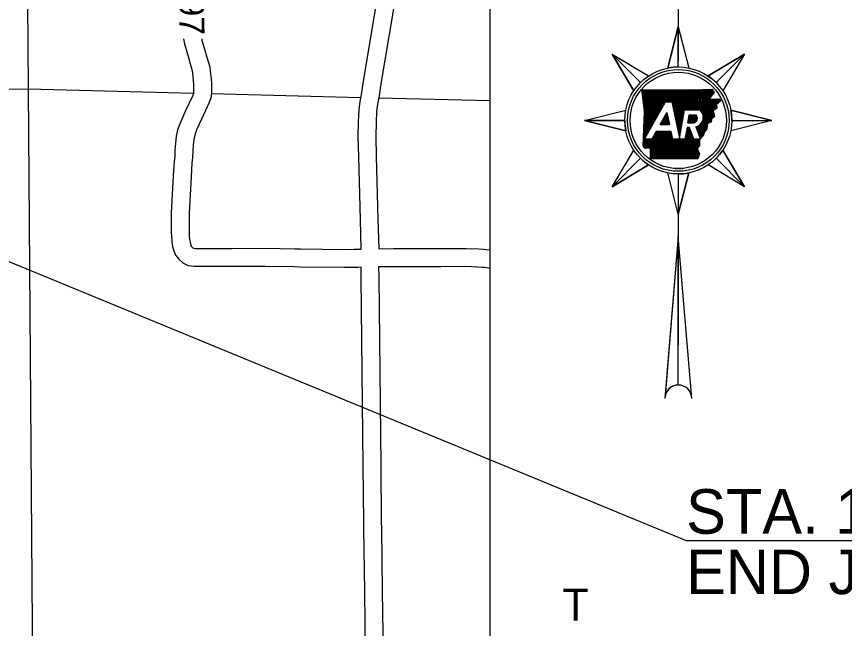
# Model space of a CAD drawing. Extents: x 1373094 to 1376427, y 1168361 to 1170494.
# Drawn here: x 1375231.7 to 1375695.7, y 1168949.6 to 1169292.6 of the extents above; entities that cross this region are included whole.
import ezdxf

# ---------------------------------------------------------------- set-up
doc = ezdxf.new("R2010")
doc.units = 0
for name, color, linetype in [('Default', 7, 'Continuous'), ('R_Axis', 7, 'Continuous'), ('R_Dimension', 7, 'Continuous'), ('R_Draft', 7, 'Continuous'), ('R_No Plot', 7, 'Continuous'), ('R_Water Annot', 7, 'Continuous')]:
    doc.layers.add(name, color=color, linetype=linetype)

msp = doc.modelspace()

# ---------------------------------------------------------------- linework, layer by layer
at = {"layer": 'R_Axis'}
for points in [[(1375491.07, 1169454.85), (1375475.9, 1169417.11), (1375468.56, 1169399.1), (1375453.78, 1169362.61), (1375441.48, 1169330.39), (1375439.61, 1169324.64), (1375437.58, 1169318.47), (1375433.53, 1169301.17), (1375433.08, 1169298.67), (1375425.81, 1169255.31), (1375425.06, 1169250.04)], [(1375496.95, 1169442.66), (1375485.17, 1169413.36), (1375477.82, 1169395.33), (1375463.09, 1169358.95), (1375450.91, 1169327.06), (1375449.11, 1169321.54), (1375447.22, 1169315.76), (1375443.32, 1169299.13), (1375442.93, 1169296.95), (1375435.69, 1169253.77), (1375434.89, 1169248.2)], [(1375237.22, 1169372.94), (1375238.19, 1169252.01), (1375240.86, 1168901.02)], [(1375325.33, 1169280.16), (1375325.76, 1169277.21), (1375328.08, 1169269.56)], [(1375335.45, 1169280.06), (1375335.55, 1169279.38), (1375337.65, 1169272.46)], [(1375337.65, 1169272.46), (1375337.87, 1169271.73), (1375338.51, 1169269.17), (1375339.95, 1169264.25), (1375340.39, 1169260.27), (1375340.69, 1169258.08), (1375340.92, 1169254.67), (1375340.91, 1169250.76), (1375340.7, 1169247.49), (1375339.64, 1169244.31), (1375335.34, 1169235.1), (1375335.34, 1169235.09)], [(1375328.08, 1169269.56), (1375328.23, 1169269.04), (1375328.87, 1169266.54), (1375330.11, 1169262.29), (1375330.46, 1169259.06), (1375330.73, 1169257.06), (1375330.92, 1169254.34), (1375330.91, 1169251.09), (1375330.8, 1169249.42), (1375330.34, 1169248.02), (1375326.28, 1169239.34), (1375326.28, 1169239.33)], [(1374905.85, 1169251.57), (1375238.19, 1169252.01), (1375330.82, 1169249.65)], [(1375340.82, 1169249.4), (1375424.54, 1169247.27)], [(1375425.06, 1169250.04), (1375424.12, 1169245.03), (1375423.48, 1169240.37), (1375423.24, 1169233.54), (1375423.04, 1169225.58), (1375423.34, 1169213.93)], [(1375434.89, 1169248.2), (1375433.99, 1169243.42), (1375433.45, 1169239.51), (1375433.24, 1169233.24), (1375433.04, 1169225.58), (1375433.34, 1169214.18)], [(1375434.67, 1169247.01), (1375496.95, 1169245.43)], [(1375326.28, 1169239.32), (1375324.91, 1169236.38), (1375323.34, 1169232.81), (1375321.98, 1169229.02), (1375321.1, 1169225.45), (1375320.69, 1169221.52), (1375320.43, 1169217.75), (1375320.36, 1169214.16), (1375320.02, 1169211.24), (1375319.56, 1169203.27)], [(1375335.34, 1169235.1), (1375334.02, 1169232.26), (1375332.64, 1169229.11), (1375331.56, 1169226.13), (1375330.97, 1169223.72), (1375330.65, 1169220.65), (1375330.42, 1169217.31), (1375330.35, 1169213.48), (1375329.99, 1169210.38), (1375329.54, 1169202.69)], [(1375433.34, 1169214.18), (1375434.24, 1169178.99)], [(1375423.34, 1169213.93), (1375424.24, 1169178.74)], [(1375319.56, 1169203.27), (1375318.35, 1169182.53), (1375318.39, 1169172.27), (1375318.52, 1169168.96), (1375318.63, 1169167.45)], [(1375329.54, 1169202.69), (1375328.36, 1169182.26), (1375328.39, 1169172.48), (1375328.5, 1169169.52), (1375328.6, 1169168.19)], [(1375424.24, 1169178.74), (1375424.67, 1169162.22)], [(1375434.24, 1169178.99), (1375434.67, 1169162.39)], [(1375328.6, 1169168.19), (1375328.65, 1169167.59), (1375328.92, 1169166.06), (1375329.4, 1169164.46), (1375329.62, 1169163.87), (1375329.99, 1169163.43), (1375330.54, 1169162.94), (1375330.94, 1169162.74), (1375331.9, 1169162.61), (1375352.38, 1169162.65)], [(1375318.63, 1169167.45), (1375318.71, 1169166.34), (1375319.18, 1169163.74), (1375319.92, 1169161.27), (1375320.86, 1169158.76), (1375322.8, 1169156.43), (1375324.9, 1169154.58), (1375327.93, 1169153.07), (1375331.22, 1169152.6), (1375352.4, 1169152.65)], [(1375352.38, 1169162.65), (1375371.2, 1169162.69), (1375387.68, 1169162.38)], [(1375387.68, 1169162.38), (1375390.8, 1169162.33), (1375415.55, 1169162.05), (1375420.65, 1169162.13), (1375422.67, 1169162.17)], [(1375422.67, 1169162.17), (1375424.67, 1169162.22)], [(1375434.67, 1169162.39), (1375443.01, 1169162.47), (1375457.98, 1169162.48)], [(1375457.98, 1169162.48), (1375469.49, 1169162.49), (1375483.64, 1169162.64), (1375490.8, 1169162.35), (1375493.5, 1169162.17)], [(1375493.5, 1169162.17), (1375494.76, 1169162.09), (1375496.95, 1169161.8)], [(1375352.4, 1169152.65), (1375371.12, 1169152.69), (1375387.5, 1169152.38)], [(1375387.5, 1169152.38), (1375390.65, 1169152.33), (1375415.57, 1169152.04), (1375420.84, 1169152.13), (1375422.9, 1169152.17)], [(1375422.9, 1169152.17), (1375424.85, 1169152.22)], [(1375424.91, 1169146.33), (1375424.85, 1169152.22)], [(1375434.84, 1169152.39), (1375443.06, 1169152.47), (1375457.98, 1169152.48)], [(1375434.9, 1169146.43), (1375434.84, 1169152.39)], [(1375457.98, 1169152.48), (1375469.55, 1169152.49), (1375483.49, 1169152.64), (1375490.27, 1169152.36), (1375492.84, 1169152.19)], [(1375492.84, 1169152.19), (1375493.79, 1169152.13), (1375496.46, 1169151.78), (1375496.95, 1169151.68)], [(1375425.26, 1169111.13), (1375424.91, 1169146.33)], [(1375435.26, 1169111.24), (1375434.9, 1169146.43)], [(1375425.62, 1169075.94), (1375425.26, 1169111.13)], [(1375435.62, 1169076.04), (1375435.26, 1169111.24)], [(1375425.98, 1169040.74), (1375425.62, 1169075.94)], [(1375435.98, 1169040.84), (1375435.62, 1169076.04)], [(1375426.35, 1169005.52), (1375426.29, 1169009.47), (1375425.98, 1169040.74)], [(1375436.35, 1169005.66), (1375436.29, 1169009.59), (1375435.98, 1169040.84)], [(1375426.86, 1168970.32), (1375426.35, 1169005.52)], [(1375436.86, 1168970.47), (1375436.35, 1169005.66)], [(1375427.37, 1168935.13), (1375426.86, 1168970.32)], [(1375437.36, 1168935.27), (1375436.86, 1168970.47)]]:
    msp.add_lwpolyline(points, dxfattribs=at)
at = {"layer": 'R_Dimension'}
for p, q in [((1374935.89, 1169275.48), (1375606.99, 1168998.81)), ((1375606.99, 1168998.81), (1375955.75, 1168998.81))]:
    msp.add_line(p, q, dxfattribs=at)
at = {"layer": 'R_Draft'}
for p, q in [((1375602.62, 1169386.03), (1375602.62, 1169267.6)), ((1375602.62, 1169286.82), (1375596.77, 1169263.75)), ((1375602.62, 1169264.32), (1375602.62, 1169286.82)), ((1375565.49, 1169271.45), (1375581.4, 1169255.54)), ((1375581.4, 1169255.54), (1375565.49, 1169271.45)), ((1375565.49, 1169271.45), (1375577.68, 1169251)), ((1375639.74, 1169271.45), (1375619.29, 1169259.26)), ((1375623.83, 1169255.54), (1375639.74, 1169271.45)), ((1375623.83, 1169255.54), (1375639.74, 1169271.45)), ((1375583.67, 1169223.82), (1375595.51, 1169244.72)), ((1375595.51, 1169244.72), (1375599.02, 1169244.72)), ((1375592.38, 1169232.02), (1375596.25, 1169238.86)), ((1375606.16, 1169240.36), (1375614.38, 1169240.36)), ((1375608.73, 1169237.41), (1375612.59, 1169237.41)), ((1375655.12, 1169234.32), (1375632.04, 1169240.17)), ((1375550.12, 1169234.32), (1375572.62, 1169234.32)), ((1375572.62, 1169234.32), (1375550.12, 1169234.32)), ((1375550.12, 1169234.32), (1375573.19, 1169228.48)), ((1375607.95, 1169232.94), (1375611.47, 1169232.94)), ((1375632.62, 1169234.32), (1375655.12, 1169234.32)), ((1375632.62, 1169234.32), (1375655.12, 1169234.32)), ((1375590.21, 1169228.2), (1375587.73, 1169223.82)), ((1375598.53, 1169228.2), (1375590.21, 1169228.2)), ((1375592.38, 1169232.02), (1375597.71, 1169232.02)), ((1375608.94, 1169230.46), (1375607.51, 1169230.46)), ((1375611.4, 1169223.82), (1375608.94, 1169230.46)), ((1375612.42, 1169230.82), (1375615.01, 1169223.82)), ((1375587.73, 1169223.82), (1375583.67, 1169223.82)), ((1375606.36, 1169223.82), (1375599.47, 1169223.82)), ((1375615.01, 1169223.82), (1375611.4, 1169223.82)), ((1375639.74, 1169197.2), (1375627.55, 1169217.65)), ((1375565.49, 1169197.2), (1375581.4, 1169213.11)), ((1375581.4, 1169213.11), (1375565.49, 1169197.2)), ((1375565.49, 1169197.2), (1375585.94, 1169209.39)), ((1375623.83, 1169213.11), (1375639.74, 1169197.2)), ((1375623.83, 1169213.11), (1375639.74, 1169197.2)), ((1375602.62, 1169181.82), (1375608.46, 1169204.9)), ((1375602.61, 1169204.32), (1375602.62, 1169204.33)), ((1375602.62, 1169204.32), (1375602.62, 1169108.29)), ((1375602.62, 1169204.32), (1375602.62, 1169181.82)), ((1375602.62, 1169169.28), (1375595.22, 1169079.77)), ((1375602.62, 1169086.03), (1375602.62, 1169169.28))]:
    msp.add_line(p, q, dxfattribs=at)
for points in [[(1375596.77, 1169263.75), (1375602.62, 1169286.82), (1375608.46, 1169263.75)], [(1375577.68, 1169251), (1375565.49, 1169271.45), (1375585.94, 1169259.26)], [(1375619.29, 1169259.26), (1375639.74, 1169271.45), (1375627.55, 1169251)], [(1375582.13, 1169251.5), (1375593.84, 1169251.49), (1375604.11, 1169251.51), (1375616.23, 1169251.7), (1375621.85, 1169251.83)], [(1375582.98, 1169219.83), (1375583.63, 1169239.47), (1375582.13, 1169251.5)], [(1375599.02, 1169244.72), (1375603.38, 1169224.37), (1375606.16, 1169240.36)], [(1375625.53, 1169246.45), (1375626.54, 1169245.39), (1375624.02, 1169243.32), (1375624.29, 1169241.22), (1375622.12, 1169239.79), (1375622.86, 1169236.57), (1375621.19, 1169235.05), (1375621.04, 1169233.39), (1375619.01, 1169232.66), (1375618.7, 1169229.54), (1375617.24, 1169227.97), (1375616.53, 1169225.62), (1375614.41, 1169223.68), (1375614.57, 1169220.25), (1375613.13, 1169218.63), (1375614.44, 1169215.68), (1375613.53, 1169212.76)], [(1375620.11, 1169246.18), (1375625.61, 1169246.46)], [(1375573.19, 1169228.48), (1375550.12, 1169234.32), (1375573.19, 1169240.17)], [(1375596.25, 1169238.86), (1375597.71, 1169232.02)], [(1375607.95, 1169232.94), (1375608.73, 1169237.41)], [(1375632.04, 1169240.17), (1375655.12, 1169234.32), (1375632.04, 1169228.48)], [(1375599.47, 1169223.82), (1375598.53, 1169228.2)], [(1375607.51, 1169230.46), (1375606.36, 1169223.82)], [(1375585.94, 1169209.39), (1375565.49, 1169197.2), (1375577.68, 1169217.65)], [(1375613.53, 1169212.76), (1375587, 1169212.8), (1375586.98, 1169218.66)], [(1375627.55, 1169217.65), (1375639.74, 1169197.2), (1375619.29, 1169209.39)], [(1375608.46, 1169204.9), (1375602.62, 1169181.82), (1375596.77, 1169204.9)], [(1375610.12, 1169078.53), (1375602.62, 1169169.28), (1375595.12, 1169078.53)]]:
    msp.add_lwpolyline(points, dxfattribs=at)
for radius in [30, 27]:
    msp.add_circle((1375602.62, 1169234.32), radius, dxfattribs=at)
for centre, radius, start, end in [((1375602.62, 1169234.32), 30, 90, 101.2291), ((1375602.62, 1169234.32), 30, 45, 56.2291), ((1375602.62, 1169234.32), 30, 135, 146.2291), ((1375610.63, 1169235.53), 2.72, 288.1268, 43.8902), ((1375611.33, 1169236.02), 5.31, 281.8626, 54.8705), ((1375602.62, 1169234.32), 30, 0, 11.2291), ((1375602.62, 1169234.32), 30, 180, 191.2291), ((1375602.62, 1169234.32), 30, 315, 326.2291), ((1375602.62, 1169234.32), 30, 225, 236.2291), ((1375602.62, 1169234.32), 30, 270, 281.2291), ((1375602.62, 1169078.53), 7.5, 0, 180), ((1375602.62, 1169078.53), 7.5, 90, 170.5511)]:
    msp.add_arc(centre, radius, start, end, dxfattribs=at)
for points in [[(1375621.85, 1169251.83), (1375621.89, 1169251.51), (1375621.99, 1169251.35), (1375622, 1169251.04), (1375622.13, 1169250.91), (1375622.34, 1169250.78), (1375622.52, 1169250.57), (1375622.57, 1169250.33), (1375622.51, 1169250.07), (1375622.49, 1169249.79), (1375622.47, 1169249.54), (1375622.42, 1169249.32), (1375622.25, 1169249.14), (1375622.08, 1169249.01), (1375621.93, 1169248.86), (1375621.82, 1169248.7), (1375621.63, 1169248.52), (1375621.45, 1169248.34), (1375621.29, 1169248.18), (1375621.14, 1169247.98), (1375621.07, 1169247.76), (1375620.9, 1169247.6), (1375620.77, 1169247.45), (1375620.6, 1169247.26), (1375620.51, 1169247.06), (1375620.34, 1169246.84), (1375620.31, 1169246.62), (1375620.2, 1169246.44), (1375620.19, 1169246.42)], [(1375586.98, 1169218.66), (1375587.01, 1169218.64), (1375586.88, 1169218.74), (1375586.69, 1169218.83), (1375586.48, 1169218.85), (1375586.21, 1169218.88), (1375585.99, 1169218.91), (1375585.75, 1169219.06), (1375585.51, 1169218.9), (1375585.23, 1169218.78), (1375585.07, 1169218.91), (1375584.86, 1169218.83), (1375584.72, 1169218.87), (1375584.47, 1169218.7), (1375584.23, 1169218.76), (1375584.05, 1169218.71), (1375583.84, 1169218.72), (1375583.79, 1169218.96), (1375583.58, 1169219), (1375583.4, 1169219.1), (1375583.28, 1169219.35), (1375583.19, 1169219.55), (1375582.98, 1169219.83)]]:
    msp.add_spline(points, degree=3, dxfattribs=at)
at = {"layer": 'R_No Plot'}
msp.add_lwpolyline([(1373989.53, 1169534.16), (1375496.95, 1169534.16), (1375496.95, 1168608.52), (1373989.53, 1168608.52)], close=True, dxfattribs=at)
at = {"layer": 'R_Water Annot'}
for p, q in [((1375582.17, 1169251.23), (1375582.43, 1169251.5)), ((1375582.26, 1169250.48), (1375583.28, 1169251.5)), ((1375582.36, 1169249.72), (1375584.13, 1169251.5)), ((1375582.45, 1169248.97), (1375584.98, 1169251.5)), ((1375582.54, 1169248.22), (1375585.82, 1169251.5)), ((1375582.64, 1169247.46), (1375586.67, 1169251.5)), ((1375582.73, 1169246.71), (1375587.52, 1169251.49)), ((1375582.83, 1169245.95), (1375588.37, 1169251.49)), ((1375582.92, 1169245.2), (1375589.22, 1169251.49)), ((1375583.01, 1169244.44), (1375590.06, 1169251.49)), ((1375583.11, 1169243.69), (1375590.91, 1169251.49)), ((1375583.2, 1169242.93), (1375591.76, 1169251.49)), ((1375583.3, 1169242.18), (1375592.61, 1169251.49)), ((1375583.39, 1169241.42), (1375593.46, 1169251.49)), ((1375583.42, 1169232.97), (1375601.96, 1169251.51)), ((1375583.45, 1169233.84), (1375601.11, 1169251.51)), ((1375583.48, 1169234.72), (1375600.26, 1169251.5)), ((1375583.48, 1169240.67), (1375594.31, 1169251.49)), ((1375583.5, 1169235.6), (1375599.41, 1169251.5)), ((1375583.53, 1169236.48), (1375598.56, 1169251.5)), ((1375583.56, 1169237.36), (1375597.71, 1169251.5)), ((1375583.58, 1169239.92), (1375595.16, 1169251.49)), ((1375583.59, 1169238.23), (1375596.86, 1169251.5)), ((1375583.62, 1169239.11), (1375596.01, 1169251.5)), ((1375596.02, 1169244.72), (1375602.81, 1169251.51)), ((1375596.87, 1169244.72), (1375603.66, 1169251.51)), ((1375597.72, 1169244.72), (1375604.51, 1169251.52)), ((1375598.56, 1169244.72), (1375605.38, 1169251.53)), ((1375599.09, 1169244.4), (1375606.24, 1169251.55)), ((1375599.24, 1169243.7), (1375607.1, 1169251.56)), ((1375599.39, 1169243), (1375607.96, 1169251.57)), ((1375599.54, 1169242.3), (1375608.82, 1169251.59)), ((1375599.69, 1169241.6), (1375609.69, 1169251.6)), ((1375599.84, 1169240.9), (1375610.55, 1169251.61)), ((1375599.99, 1169240.21), (1375611.41, 1169251.63)), ((1375600.14, 1169239.51), (1375612.27, 1169251.64)), ((1375600.29, 1169238.81), (1375613.13, 1169251.65)), ((1375600.44, 1169238.11), (1375614, 1169251.67)), ((1375600.59, 1169237.41), (1375614.86, 1169251.68)), ((1375600.74, 1169236.71), (1375615.72, 1169251.69)), ((1375600.89, 1169236.01), (1375616.58, 1169251.71)), ((1375601.04, 1169235.31), (1375617.45, 1169251.73)), ((1375606.93, 1169240.36), (1375618.32, 1169251.75)), ((1375607.78, 1169240.36), (1375619.19, 1169251.77)), ((1375608.63, 1169240.36), (1375620.06, 1169251.79)), ((1375609.48, 1169240.36), (1375620.93, 1169251.81)), ((1375610.33, 1169240.36), (1375621.8, 1169251.83)), ((1375611.17, 1169240.36), (1375621.99, 1169251.17)), ((1375612.02, 1169240.36), (1375622.4, 1169250.73)), ((1375612.87, 1169240.36), (1375622.51, 1169249.99)), ((1375613.72, 1169240.36), (1375620.57, 1169247.21)), ((1375583.39, 1169232.09), (1375594.84, 1169243.54)), ((1375614.49, 1169240.28), (1375620.4, 1169246.19)), ((1375614.95, 1169239.9), (1375621.3, 1169246.24)), ((1375615.37, 1169239.46), (1375622.19, 1169246.28)), ((1375615.73, 1169238.98), (1375623.08, 1169246.33)), ((1375616.05, 1169238.45), (1375623.98, 1169246.38)), ((1375616.31, 1169237.86), (1375624.87, 1169246.42)), ((1375616.45, 1169234.6), (1375624.15, 1169242.3)), ((1375616.5, 1169237.2), (1375625.68, 1169246.38)), ((1375616.62, 1169236.47), (1375626.08, 1169245.93)), ((1375616.62, 1169235.63), (1375624.05, 1169243.05)), ((1375625.7, 1169244.7), (1375626.47, 1169245.47)), ((1375583.3, 1169229.46), (1375591.51, 1169237.67)), ((1375583.33, 1169230.33), (1375592.62, 1169239.63)), ((1375583.36, 1169231.21), (1375593.73, 1169241.58)), ((1375594.54, 1169235.84), (1375596.48, 1169237.78)), ((1375595.65, 1169237.79), (1375596.33, 1169238.48)), ((1375601.19, 1169234.61), (1375606, 1169239.43)), ((1375601.34, 1169233.91), (1375605.82, 1169238.4)), ((1375601.49, 1169233.22), (1375605.64, 1169237.37)), ((1375607.95, 1169232.94), (1375612.42, 1169237.41)), ((1375608.13, 1169233.97), (1375611.57, 1169237.41)), ((1375608.3, 1169234.99), (1375610.72, 1169237.41)), ((1375608.48, 1169236.02), (1375609.87, 1169237.41)), ((1375608.66, 1169237.05), (1375609.02, 1169237.41)), ((1375612.94, 1169229.4), (1375622.35, 1169238.81)), ((1375613.17, 1169228.78), (1375622.51, 1169238.12)), ((1375613.4, 1169228.16), (1375622.67, 1169237.43)), ((1375615.71, 1169233.01), (1375622.19, 1169239.5)), ((1375623.2, 1169240.5), (1375624.25, 1169241.55)), ((1375583.24, 1169227.7), (1375589.3, 1169233.76)), ((1375583.27, 1169228.58), (1375590.41, 1169235.71)), ((1375592.42, 1169232.02), (1375596.78, 1169236.38)), ((1375593.27, 1169232.02), (1375596.93, 1169235.68)), ((1375593.43, 1169233.88), (1375596.63, 1169237.08)), ((1375594.11, 1169232.02), (1375597.08, 1169234.98)), ((1375594.96, 1169232.02), (1375597.23, 1169234.28)), ((1375595.81, 1169232.02), (1375597.38, 1169233.59)), ((1375596.66, 1169232.02), (1375597.53, 1169232.89)), ((1375601.63, 1169232.52), (1375605.46, 1169236.35)), ((1375601.78, 1169231.82), (1375605.28, 1169235.32)), ((1375601.93, 1169231.12), (1375605.11, 1169234.29)), ((1375602.08, 1169230.42), (1375604.93, 1169233.26)), ((1375608.8, 1169232.94), (1375612.89, 1169237.03)), ((1375609.65, 1169232.94), (1375613.17, 1169236.47)), ((1375610.5, 1169232.94), (1375613.33, 1169235.78)), ((1375611.35, 1169232.94), (1375613.26, 1169234.86)), ((1375613.63, 1169227.54), (1375622.83, 1169236.74)), ((1375619.93, 1169232.99), (1375621.12, 1169234.18)), ((1375583.18, 1169225.95), (1375587.08, 1169229.85)), ((1375583.21, 1169226.82), (1375588.19, 1169231.8)), ((1375583.31, 1169219.28), (1375592.23, 1169228.2)), ((1375583.81, 1169218.94), (1375593.08, 1169228.2)), ((1375584.42, 1169218.7), (1375593.93, 1169228.2)), ((1375585.43, 1169218.86), (1375594.77, 1169228.2)), ((1375586.29, 1169218.87), (1375595.62, 1169228.2)), ((1375586.96, 1169218.69), (1375596.47, 1169228.2)), ((1375586.99, 1169217.02), (1375598.17, 1169228.2)), ((1375586.99, 1169217.87), (1375597.32, 1169228.2)), ((1375588.69, 1169225.52), (1375591.38, 1169228.2)), ((1375589.8, 1169227.47), (1375590.53, 1169228.2)), ((1375597.51, 1169232.02), (1375597.68, 1169232.19)), ((1375602.23, 1169229.72), (1375604.75, 1169232.24)), ((1375602.38, 1169229.02), (1375604.57, 1169231.21)), ((1375602.53, 1169228.32), (1375604.39, 1169230.18)), ((1375602.68, 1169227.62), (1375604.21, 1169229.15)), ((1375602.83, 1169226.93), (1375604.03, 1169228.13)), ((1375606.5, 1169224.66), (1375609.85, 1169228)), ((1375606.68, 1169225.68), (1375609.62, 1169228.62)), ((1375606.86, 1169226.71), (1375609.39, 1169229.24)), ((1375607.04, 1169227.74), (1375609.16, 1169229.86)), ((1375607.22, 1169228.77), (1375608.92, 1169230.46)), ((1375607.4, 1169229.8), (1375608.07, 1169230.46)), ((1375612.49, 1169230.64), (1375612.74, 1169230.9)), ((1375612.71, 1169230.02), (1375614.33, 1169231.63)), ((1375613.86, 1169226.92), (1375618.95, 1169232.01)), ((1375614.09, 1169226.3), (1375618.85, 1169231.07)), ((1375614.32, 1169225.68), (1375618.76, 1169230.12)), ((1375582.99, 1169219.82), (1375586.99, 1169223.82)), ((1375583.01, 1169220.68), (1375586.15, 1169223.82)), ((1375583.04, 1169221.56), (1375585.3, 1169223.82)), ((1375583.07, 1169222.44), (1375584.45, 1169223.82)), ((1375583.1, 1169223.31), (1375583.76, 1169223.98)), ((1375583.13, 1169224.19), (1375584.87, 1169225.93)), ((1375583.16, 1169225.07), (1375585.98, 1169227.89)), ((1375586.99, 1169216.18), (1375598.61, 1169227.8)), ((1375586.99, 1169215.33), (1375598.76, 1169227.1)), ((1375587, 1169214.48), (1375598.91, 1169226.4)), ((1375587, 1169213.64), (1375599.06, 1169225.7)), ((1375587.01, 1169212.8), (1375599.21, 1169225)), ((1375587.86, 1169212.8), (1375599.36, 1169224.31)), ((1375588.71, 1169212.8), (1375599.72, 1169223.82)), ((1375589.55, 1169212.8), (1375600.57, 1169223.82)), ((1375590.4, 1169212.8), (1375601.42, 1169223.82)), ((1375591.25, 1169212.8), (1375602.27, 1169223.82)), ((1375592.09, 1169212.79), (1375603.12, 1169223.82)), ((1375592.94, 1169212.79), (1375603.96, 1169223.82)), ((1375593.79, 1169212.79), (1375604.81, 1169223.82)), ((1375594.64, 1169212.79), (1375605.66, 1169223.82)), ((1375595.48, 1169212.79), (1375610.08, 1169227.38)), ((1375596.33, 1169212.79), (1375610.31, 1169226.76)), ((1375597.18, 1169212.79), (1375610.54, 1169226.14)), ((1375598.02, 1169212.78), (1375610.76, 1169225.52)), ((1375598.87, 1169212.78), (1375610.99, 1169224.9)), ((1375599.72, 1169212.78), (1375611.22, 1169224.29)), ((1375600.57, 1169212.78), (1375611.6, 1169223.82)), ((1375601.41, 1169212.78), (1375612.45, 1169223.82)), ((1375602.26, 1169212.78), (1375613.3, 1169223.82)), ((1375602.98, 1169226.23), (1375603.85, 1169227.1)), ((1375603.11, 1169212.78), (1375614.15, 1169223.82)), ((1375603.13, 1169225.53), (1375603.67, 1169226.07)), ((1375603.28, 1169224.83), (1375603.49, 1169225.04)), ((1375614.55, 1169225.06), (1375617.15, 1169227.66)), ((1375614.77, 1169224.44), (1375616.78, 1169226.45)), ((1375603.95, 1169212.77), (1375614.43, 1169223.25)), ((1375604.8, 1169212.77), (1375614.47, 1169222.44)), ((1375605.65, 1169212.77), (1375614.51, 1169221.63)), ((1375606.5, 1169212.77), (1375614.54, 1169220.82)), ((1375607.34, 1169212.77), (1375613.15, 1169218.58)), ((1375608.19, 1169212.77), (1375613.41, 1169217.99)), ((1375609.04, 1169212.77), (1375613.67, 1169217.4)), ((1375609.88, 1169212.77), (1375613.94, 1169216.82)), ((1375610.73, 1169212.76), (1375614.2, 1169216.23)), ((1375611.58, 1169212.76), (1375614.42, 1169215.6)), ((1375612.43, 1169212.76), (1375614.03, 1169214.37)), ((1375613.27, 1169212.76), (1375613.65, 1169213.14))]:
    msp.add_line(p, q, dxfattribs=at)
msp.add_circle((1375602.62, 1169234.32), 28.5, dxfattribs=at)

# ---------------------------------------------------------------- texts
at = {"layer": 'Default'}
msp.add_text('T', height=18, dxfattribs=at).set_placement((1375537.67, 1168953.98))
at = {"layer": 'R_Dimension'}
for s, p in [('STA. 110+23.00', (1375606.99, 1169002.69)), ('END JOB 070510', (1375606.99, 1168968.83))]:
    msp.add_text(s, height=25, rotation=0.0006, dxfattribs=at).set_placement(p)
at = {"layer": 'R_Draft'}
msp.add_text('DWB 7-27-17', height=0.5833, dxfattribs=at).set_placement((1375600.78, 1169206.82))
at = {"layer": 'R_Water Annot'}
msp.add_text('CO. RD. 297', height=14.08, rotation=270.3797, dxfattribs=at).set_placement((1375322.26, 1169389.96))

doc.saveas('drawing.dxf')
